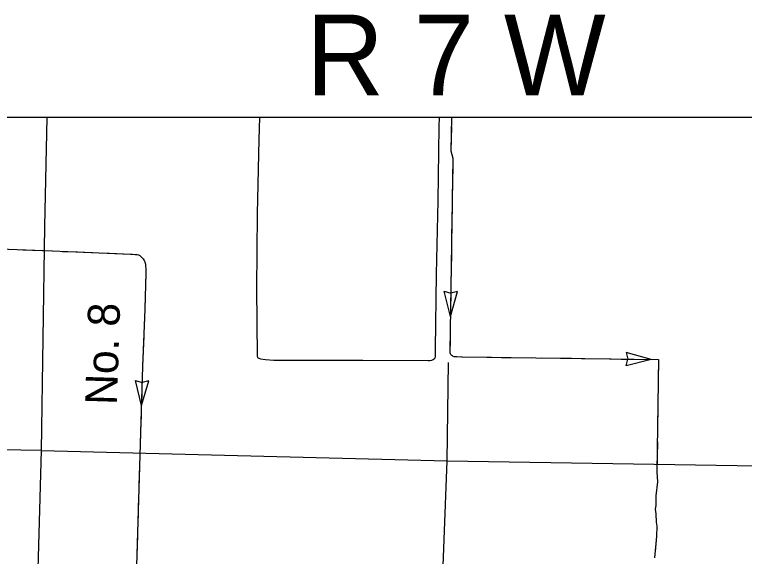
# Model space of a CAD drawing. Extents: x 1196286 to 1268366, y 2040822 to 2082115.
# Drawn here: x 1218140 to 1221760, y 2063420 to 2066107 of the extents above; entities that cross this region are included whole.
import ezdxf

# ---------------------------------------------------------------- set-up
doc = ezdxf.new("R2010")
doc.units = 0
for name, color, linetype in [('26', 7, 'Continuous'), ('60', 7, 'Continuous'), ('62', 7, 'Continuous'), ('63', 7, 'Continuous'), ('Level 8', 7, 'Continuous')]:
    doc.layers.add(name, color=color, linetype=linetype)

msp = doc.modelspace()

# ---------------------------------------------------------------- linework, layer by layer
at = {"layer": '60'}
for points in [[(1218300, 2065596.8), (1218288, 2065056.5), (1218272.3, 2063944.2)], [(1220286.5, 2063894.5), (1220292.1, 2064381.6)], [(1218272.3, 2063944.2), (1216366.3, 2063976)], [(1218272.3, 2063944.2), (1218218.5, 2062063.5)], [(1218272.3, 2063944.2), (1220286.5, 2063894.5)], [(1220211.7, 2061943.6), (1220286.5, 2063894.5)], [(1220286.5, 2063894.5), (1222133.3, 2063864.7)]]:
    msp.add_lwpolyline(points, dxfattribs=at)
at = {"layer": '62'}
msp.add_line((1220247.2, 2065596.8), (1219354.6, 2065596.8), dxfattribs=at)
msp.add_lwpolyline([(1219354.6, 2065596.8), (1219352.3, 2065487.7), (1219343.4, 2065117.9), (1219339.5, 2064749.2), (1219342.7, 2064413.4), (1219344.9, 2064407), (1219351.6, 2064402.3), (1219359.6, 2064399.5), (1219384, 2064396.5), (1219425.8, 2064392.2), (1219867.9, 2064392.8), (1220191.4, 2064391.5), (1220199.5, 2064391.1), (1220209.6, 2064392.6), (1220216.1, 2064396), (1220223.9, 2064403.2), (1220227.3, 2064408.7), (1220228.3, 2064418.1), (1220227.7, 2064448.9), (1220233.5, 2064818.8), (1220240.4, 2065183.1), (1220246.7, 2065549.8), (1220247.2, 2065596.8)], dxfattribs=at)
at = {"layer": '63'}
for p, q in [((1220301.9, 2064610.3), (1220270.5, 2064735.1)), ((1220270.5, 2064735.1), (1220303.5, 2064725.8)), ((1220301.9, 2064610.3), (1220337.1, 2064734.1)), ((1220337.1, 2064734.1), (1220303.9, 2064725.8)), ((1221297.8, 2064396.5), (1221173.9, 2064431.6)), ((1221173.9, 2064431.6), (1221182.3, 2064398.4)), ((1221173, 2064365), (1221182.3, 2064397.9)), ((1221297.8, 2064396.5), (1221173, 2064365)), ((1218769, 2064167.5), (1218739.6, 2064292.8)), ((1218739.6, 2064292.8), (1218772.4, 2064282.9)), ((1218769, 2064167.5), (1218806.1, 2064290.7)), ((1218806.1, 2064290.7), (1218772.8, 2064282.9))]:
    msp.add_line(p, q, dxfattribs=at)
for points in [[(1220307.7, 2065596.8), (1220303.9, 2065430.8), (1220313.9, 2065394.1), (1220299.3, 2064436.1), (1220298.7, 2064430.4), (1220300.2, 2064425.8), (1220302.6, 2064422.3), (1220306.4, 2064418.4), (1220309.7, 2064415.5), (1220314.1, 2064413), (1220318.9, 2064411.6), (1220325.4, 2064411.1), (1220333.9, 2064410.4), (1220359.4, 2064409.6), (1221334.3, 2064396), (1221326, 2063838.9), (1221328.2, 2063789.3), (1221321, 2063720.3), (1221320.3, 2063672.2), (1221316.7, 2063654), (1221319.8, 2063631.3), (1221321.7, 2063590), (1221325.7, 2063569.2), (1221323.6, 2063520.7), (1221314.1, 2063413.2)], [(1220306.6, 2065549.4), (1220303.9, 2065430.8), (1220311.8, 2065402)], [(1220313.3, 2065352.7), (1220311, 2065204.3)], [(1220310.3, 2065154.8), (1220308, 2065006.3)], [(1217544.5, 2064965.1), (1218326.4, 2064934.7), (1218714.6, 2064919.1), (1218738.5, 2064916.7), (1218747.4, 2064916.4), (1218755.2, 2064915), (1218760.7, 2064911.9), (1218766.6, 2064906.6), (1218773.4, 2064899.9), (1218778.5, 2064894.7), (1218783.5, 2064887.8), (1218786.1, 2064881.2), (1218788.8, 2064869), (1218790.1, 2064858.3), (1218791.1, 2064847.6), (1218791.2, 2064825.9), (1218786.1, 2064645.5), (1218775, 2064362), (1218756.3, 2063757.3), (1218738.7, 2063154.7)], [(1218180.5, 2064940.4), (1218326.4, 2064934.7), (1218328.9, 2064934.6)], [(1218378.4, 2064932.6), (1218452.6, 2064929.6)], [(1218452.6, 2064929.6), (1218526.8, 2064926.7)], [(1218576.2, 2064924.7), (1218714.6, 2064919.1), (1218724.6, 2064918.1)], [(1220307.2, 2064956.8), (1220305, 2064808.3)], [(1218769.8, 2064903.5), (1218773.4, 2064899.9), (1218778.5, 2064894.7), (1218783.5, 2064887.8), (1218786.1, 2064881.2), (1218788.8, 2064869), (1218790.1, 2064858.3), (1218791.1, 2064847.6), (1218791.2, 2064825.9), (1218789.4, 2064761.2)], [(1220304.2, 2064758.8), (1220301.9, 2064610.3)], [(1218788, 2064711.7), (1218786.1, 2064645.5), (1218782.9, 2064563.3)], [(1220301.2, 2064560.8), (1220300, 2064486.6)], [(1218781, 2064513.8), (1218775.2, 2064365.4)], [(1220300, 2064486.6), (1220299.3, 2064436.1), (1220298.7, 2064430.4), (1220300.2, 2064425.8), (1220302.6, 2064422.3), (1220306.4, 2064418.4), (1220309, 2064416.1)], [(1220357.3, 2064409.7), (1220359.4, 2064409.6), (1220505.8, 2064407.6)], [(1220555.3, 2064406.9), (1220703.8, 2064404.8)], [(1220753.3, 2064404.1), (1220901.8, 2064402.1)], [(1220951.3, 2064401.4), (1221099.8, 2064399.3)], [(1221149.3, 2064398.6), (1221297.8, 2064396.5)], [(1221334.1, 2064383.1), (1221333, 2064308.9)], [(1218773.6, 2064315.9), (1218769, 2064167.5)], [(1221333, 2064308.9), (1221331.9, 2064234.6)], [(1221331.2, 2064185.1), (1221329, 2064036.7)], [(1218767.5, 2064118), (1218765.2, 2064043.8)], [(1218765.2, 2064043.8), (1218762.9, 2063969.6)], [(1221328.2, 2063987.2), (1221326, 2063838.9), (1221326, 2063838.7)], [(1218761.4, 2063920.1), (1218756.8, 2063771.7)], [(1221328.1, 2063789.2), (1221321, 2063720.3), (1221320.3, 2063672.2), (1221316.7, 2063654), (1221318.4, 2063641.6)], [(1218755.3, 2063722.2), (1218751, 2063573.8)], [(1221321.6, 2063592.2), (1221321.7, 2063590), (1221325.7, 2063569.2), (1221323.6, 2063520.7), (1221316.9, 2063444.4)], [(1218749.5, 2063524.3), (1218745.2, 2063375.9)]]:
    msp.add_lwpolyline(points, dxfattribs=at)
at = {"layer": 'Level 8'}
msp.add_lwpolyline([(1241590.6, 2065596.8), (1214332.8, 2065596.8), (1214332.8, 2047966.3), (1241590.6, 2047966.3)], close=True, dxfattribs=at)

# ---------------------------------------------------------------- texts
at = {"layer": '26'}
msp.add_text('R 7 W', height=400, dxfattribs=at).set_placement((1219586.1, 2065706.7))
at = {"layer": '63'}
msp.add_text('No. 8', height=158.4, rotation=88.2181, dxfattribs=at).set_placement((1218647.9, 2064169.2))

doc.saveas('drawing.dxf')
